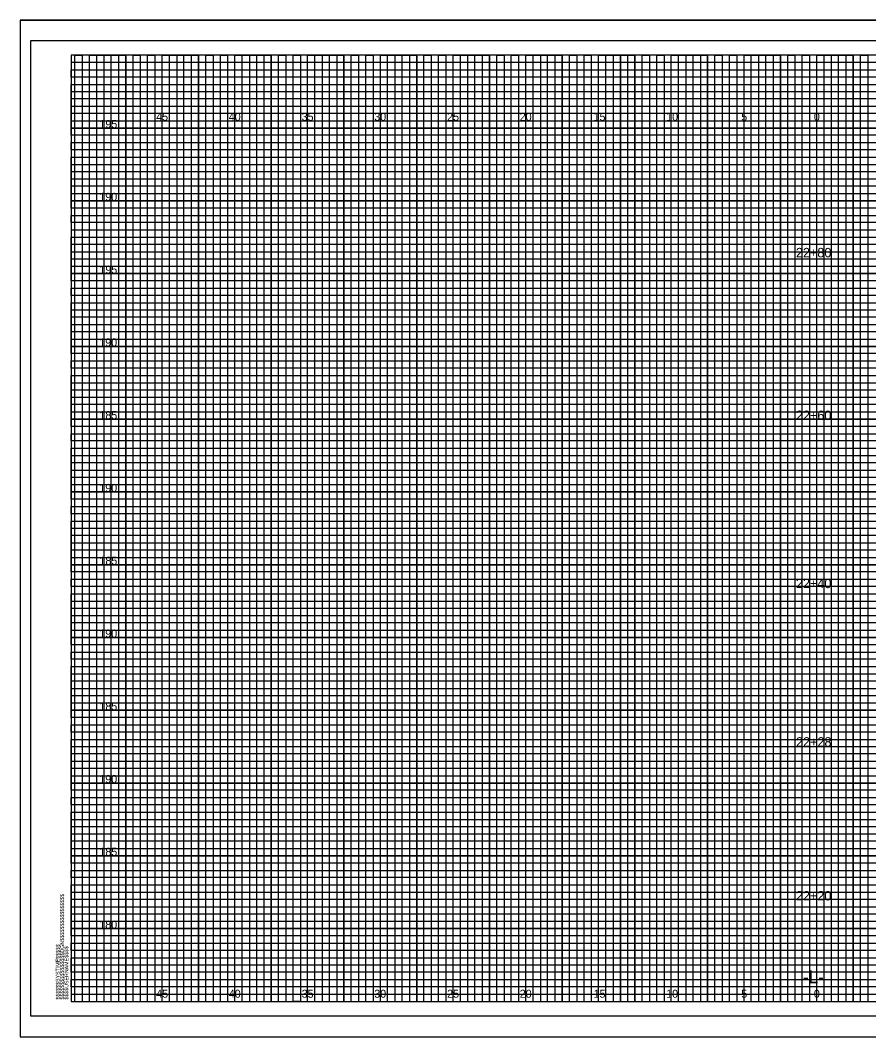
# Model space of a CAD drawing. Extents: x -4 to 103, y -2 to 6583.
# Drawn here: x -3.5 to 54.8, y 1201.6 to 1271.4 of the extents above; entities that cross this region are included whole.
import ezdxf

# ---------------------------------------------------------------- set-up
doc = ezdxf.new("R2010")
doc.units = 0
for name, color, linetype in [('Prop XS Alignment Label', 7, 'Continuous'), ('Prop XS Elevation Labels', 7, 'Continuous'), ('Prop XS Offset Labels', 7, 'Continuous'), ('Prop XS Station Labels', 7, 'Continuous'), ('Sheet Cross Section CELL', 7, 'Continuous'), ('Sheet Cross Section Grid Major CELL', 7, 'Continuous'), ('Sheet Cross Section Grid Middle CELL', 7, 'Continuous'), ('Sheet Cutting Line CELL', 7, 'Continuous'), ('Sheet DOT Grid CELL', 7, 'Continuous'), ('Sheet Plot Border Inside CELL', 7, 'Continuous'), ('Sheet Plot Border Outside CELL', 7, 'Continuous')]:
    doc.layers.add(name, color=color, linetype=linetype)

msp = doc.modelspace()

# ---------------------------------------------------------------- linework, layer by layer
at = {"layer": 'Sheet Cross Section CELL'}
msp.add_lwpolyline([(102.5, 1269.025), (0, 1269.025), (0, 1204.025), (102.5, 1204.025)], close=True, dxfattribs=at)
at = {"layer": 'Sheet Cross Section Grid Major CELL'}
for points in [[(1.25, 1204.025), (1.25, 1269.025), (3.75, 1269.025), (3.75, 1204.025), (6.25, 1204.025), (6.25, 1269.025), (8.75, 1269.025), (8.75, 1204.025), (11.25, 1204.025), (11.25, 1269.025), (13.75, 1269.025), (13.75, 1204.025), (16.25, 1204.025), (16.25, 1269.025), (18.75, 1269.025), (18.75, 1204.025), (21.25, 1204.025), (21.25, 1269.025), (23.75, 1269.025), (23.75, 1204.025), (26.25, 1204.025), (26.25, 1269.025), (28.75, 1269.025), (28.75, 1204.025), (31.25, 1204.025), (31.25, 1269.025), (33.75, 1269.025), (33.75, 1204.025), (36.25, 1204.025), (36.25, 1269.025), (38.75, 1269.025), (38.75, 1204.025), (41.25, 1204.025), (41.25, 1269.025), (43.75, 1269.025), (43.75, 1204.025), (46.25, 1204.025), (46.25, 1269.025), (48.75, 1269.025), (48.75, 1204.025), (51.25, 1204.025), (51.25, 1269.025), (53.75, 1269.025), (53.75, 1204.025)], [(102.5, 1264.025), (0, 1264.025), (0, 1266.525), (74.25, 1266.525)], [(102.5, 1259.025), (0, 1259.025), (0, 1261.525), (102.5, 1261.525)], [(102.5, 1254.025), (0, 1254.025), (0, 1256.525), (102.5, 1256.525)], [(102.5, 1249.025), (0, 1249.025), (0, 1251.525), (102.5, 1251.525)], [(102.5, 1244.025), (0, 1244.025), (0, 1246.525), (102.5, 1246.525)], [(102.5, 1239.025), (0, 1239.025), (0, 1241.525), (102.5, 1241.525)], [(102.5, 1234.025), (0, 1234.025), (0, 1236.525), (102.5, 1236.525)], [(102.5, 1229.025), (0, 1229.025), (0, 1231.525), (102.5, 1231.525)], [(102.5, 1224.025), (0, 1224.025), (0, 1226.525), (102.5, 1226.525)], [(102.5, 1219.025), (0, 1219.025), (0, 1221.525), (102.5, 1221.525)], [(102.5, 1214.025), (0, 1214.025), (0, 1216.525), (102.5, 1216.525)], [(102.5, 1209.025), (0, 1209.025), (0, 1211.525), (102.5, 1211.525)], [(0, 1206.525), (102.5, 1206.525)]]:
    msp.add_lwpolyline(points, dxfattribs=at)
at = {"layer": 'Sheet Cross Section Grid Middle CELL'}
for points in [[(0.25, 1204.025), (0.25, 1269.025), (0.75, 1269.025), (0.75, 1204.025), (1.75, 1204.025), (1.75, 1269.025), (2.25, 1269.025), (2.25, 1204.025), (2.75, 1204.025), (2.75, 1269.025), (3.25, 1269.025), (3.25, 1204.025), (4.25, 1204.025), (4.25, 1269.025), (4.75, 1269.025), (4.75, 1204.025), (5.25, 1204.025), (5.25, 1269.025), (5.75, 1269.025), (5.75, 1204.025), (6.75, 1204.025), (6.75, 1269.025), (7.25, 1269.025), (7.25, 1204.025), (7.75, 1204.025), (7.75, 1269.025), (8.25, 1269.025), (8.25, 1204.025), (9.25, 1204.025), (9.25, 1269.025), (9.75, 1269.025), (9.75, 1204.025), (10.25, 1204.025), (10.25, 1269.025), (10.75, 1269.025), (10.75, 1204.025), (11.75, 1204.025), (11.75, 1269.025), (12.25, 1269.025), (12.25, 1204.025), (12.75, 1204.025), (12.75, 1269.025), (13.25, 1269.025), (13.25, 1204.025), (14.25, 1204.025), (14.25, 1269.025), (14.75, 1269.025), (14.75, 1204.025), (15.75, 1204.025), (15.25, 1204.025), (15.25, 1269.025), (15.75, 1269.025), (15.75, 1204.025), (16.75, 1204.025), (16.75, 1269.025), (17.25, 1269.025), (17.25, 1204.025), (17.75, 1204.025), (17.75, 1269.025), (18.25, 1269.025), (18.25, 1204.025), (19.25, 1204.025), (19.25, 1269.025), (19.75, 1269.025), (19.75, 1204.025), (20.25, 1204.025), (20.25, 1269.025), (20.75, 1269.025), (20.75, 1204.025), (21.75, 1204.025), (21.75, 1269.025), (22.25, 1269.025), (22.25, 1204.025), (22.75, 1204.025), (22.75, 1269.025), (23.25, 1269.025), (23.25, 1204.025), (24.25, 1204.025), (24.25, 1269.025), (24.75, 1269.025), (24.75, 1204.025), (25.25, 1204.025), (25.25, 1269.025), (25.75, 1269.025), (25.75, 1204.025), (26.75, 1204.025), (26.75, 1269.025), (27.25, 1269.025), (27.25, 1204.025), (27.75, 1204.025), (27.75, 1269.025), (28.25, 1269.025), (28.25, 1204.025), (29.25, 1204.025), (29.25, 1269.025), (29.75, 1269.025), (29.75, 1204.025), (30.25, 1204.025), (30.25, 1269.025), (30.75, 1269.025), (30.75, 1204.025)], [(30.75, 1204.025), (31.75, 1204.025), (31.75, 1269.025), (32.25, 1269.025), (32.25, 1204.025), (32.75, 1204.025), (32.75, 1269.025), (33.25, 1269.025), (33.25, 1204.025), (34.25, 1204.025), (34.25, 1269.025), (34.75, 1269.025), (34.75, 1204.025), (35.25, 1204.025), (35.25, 1269.025), (35.75, 1269.025), (35.75, 1204.025), (36.75, 1204.025), (36.75, 1269.025), (37.25, 1269.025), (37.25, 1204.025), (37.75, 1204.025), (37.75, 1269.025), (37.75, 1204.025)], [(38.25, 1269.025), (38.25, 1204.025), (39.25, 1204.025), (39.25, 1269.025), (39.75, 1269.025), (39.75, 1204.025), (40.25, 1204.025), (40.25, 1269.025), (40.75, 1269.025), (40.75, 1204.025), (41.75, 1204.025), (41.75, 1269.025), (42.25, 1269.025), (42.25, 1204.025), (42.75, 1204.025), (42.75, 1269.025), (43.25, 1269.025), (43.25, 1204.025), (43.75, 1204.025), (44.25, 1204.025), (44.25, 1269.025), (44.75, 1269.025), (44.75, 1204.025), (45.25, 1204.025), (45.25, 1269.025), (45.75, 1269.025), (45.75, 1204.025), (46.75, 1204.025), (46.75, 1269.025), (47.25, 1269.025), (47.25, 1204.025), (47.75, 1204.025), (47.75, 1269.025), (48.25, 1269.025), (48.25, 1204.025), (49.25, 1204.025), (49.25, 1269.025), (49.75, 1269.025), (49.75, 1204.025), (50.25, 1204.025), (50.25, 1269.025), (50.75, 1269.025), (50.75, 1204.025), (51.75, 1204.025), (51.75, 1269.025), (52.25, 1269.025), (52.25, 1204.025), (52.75, 1204.025), (52.75, 1269.025), (53.25, 1269.025), (53.25, 1204.025), (54.25, 1204.025), (54.25, 1269.025), (54.75, 1269.025), (54.75, 1204.025), (55.25, 1204.025)], [(0, 1266.025), (0, 1267.025), (74.25, 1267.025), (74.25, 1267.525), (0, 1267.525), (0, 1268.025), (74.25, 1268.025), (74.25, 1268.525), (0, 1268.525)], [(102.5, 1266.025), (0, 1266.025)], [(102.5, 1265.025), (0, 1265.025), (0, 1265.525), (102.5, 1265.525)], [(102.5, 1263.525), (0, 1263.525), (0, 1264.525), (102.5, 1264.525)], [(102.5, 1262.525), (0, 1262.525), (0, 1263.025), (102.5, 1263.025)], [(102.5, 1261.025), (0, 1261.025), (0, 1262.025), (102.5, 1262.025)], [(102.5, 1260.025), (0, 1260.025), (0, 1260.525), (102.5, 1260.525)], [(102.5, 1258.525), (0, 1258.525), (0, 1259.525), (102.5, 1259.525)], [(102.5, 1257.525), (0, 1257.525), (0, 1258.025), (102.5, 1258.025)], [(0, 1257.025), (102.5, 1257.025)], [(102.5, 1256.025), (0, 1256.025)], [(102.5, 1255.025), (0, 1255.025), (0, 1255.525), (102.5, 1255.525)], [(102.5, 1253.525), (0, 1253.525), (0, 1254.525), (102.5, 1254.525)], [(102.5, 1252.525), (0, 1252.525), (0, 1253.025), (102.5, 1253.025)], [(102.5, 1251.025), (0, 1251.025), (0, 1252.025), (102.5, 1252.025)], [(102.5, 1250.025), (0, 1250.025), (0, 1250.525), (102.5, 1250.525)], [(102.5, 1248.525), (0, 1248.525), (0, 1249.525), (102.5, 1249.525)], [(102.5, 1247.525), (0, 1247.525), (0, 1248.025), (102.5, 1248.025)], [(102.5, 1246.025), (0, 1246.025), (0, 1247.025), (102.5, 1247.025)], [(102.5, 1245.025), (0, 1245.025), (0, 1245.525), (102.5, 1245.525)], [(102.5, 1243.525), (0, 1243.525), (0, 1244.525), (102.5, 1244.525)], [(102.5, 1242.525), (0, 1242.525), (0, 1243.025), (102.5, 1243.025)], [(102.5, 1241.025), (0, 1241.025), (0, 1242.025), (102.5, 1242.025)], [(102.5, 1240.025), (0, 1240.025), (0, 1240.525), (102.5, 1240.525)], [(102.5, 1238.525), (0, 1238.525), (0, 1239.525), (102.5, 1239.525)], [(102.5, 1237.525), (0, 1237.525), (0, 1238.025), (102.5, 1238.025)], [(102.5, 1236.025), (0, 1236.025), (0, 1237.025), (102.5, 1237.025)], [(102.5, 1235.025), (0, 1235.025), (0, 1235.525)], [(0, 1235.525), (102.5, 1235.525)], [(102.5, 1233.525), (0, 1233.525), (0, 1234.525), (102.5, 1234.525)], [(102.5, 1232.525), (0, 1232.525), (0, 1233.025), (102.5, 1233.025)], [(102.5, 1231.025), (0, 1231.025), (0, 1232.025), (102.5, 1232.025)], [(102.5, 1230.025), (0, 1230.025), (0, 1230.525), (102.5, 1230.525)], [(102.5, 1228.525), (0, 1228.525), (0, 1229.525), (102.5, 1229.525)], [(102.5, 1227.525), (0, 1227.525), (0, 1228.025), (102.5, 1228.025)], [(102.5, 1226.025), (0, 1226.025), (0, 1227.025), (102.5, 1227.025)], [(102.5, 1225.025), (0, 1225.025), (0, 1225.525), (102.5, 1225.525)], [(102.5, 1223.525), (0, 1223.525), (0, 1224.525), (102.5, 1224.525)], [(102.5, 1222.525), (0, 1222.525), (0, 1223.025), (102.5, 1223.025)], [(102.5, 1221.025), (0, 1221.025), (0, 1222.025), (102.5, 1222.025)], [(102.5, 1220.025), (0, 1220.025), (0, 1220.525), (102.5, 1220.525)], [(102.5, 1218.525), (0, 1218.525), (0, 1219.525), (102.5, 1219.525)], [(102.5, 1217.525), (0, 1217.525), (0, 1218.025), (102.5, 1218.025)], [(102.5, 1216.025), (0, 1216.025), (0, 1217.025), (102.5, 1217.025)], [(102.5, 1215.025), (0, 1215.025), (0, 1215.525), (102.5, 1215.525)], [(102.5, 1213.525), (0, 1213.525), (0, 1214.525), (102.5, 1214.525)], [(102.5, 1212.525), (0, 1212.525), (0, 1213.025), (102.5, 1213.025)], [(102.5, 1211.025), (0, 1211.025), (0, 1212.025), (102.5, 1212.025)], [(102.5, 1210.025), (0, 1210.025), (0, 1210.525), (102.5, 1210.525)], [(102.5, 1208.525), (0, 1208.525), (0, 1209.525), (102.5, 1209.525)], [(102.5, 1207.525), (0, 1207.525), (0, 1208.025), (102.5, 1208.025)], [(102.5, 1206.025), (0, 1206.025), (0, 1207.025), (102.5, 1207.025)], [(102.5, 1205.025), (0, 1205.025), (0, 1205.525), (102.5, 1205.525)], [(0, 1204.525), (102.5, 1204.525)]]:
    msp.add_lwpolyline(points, dxfattribs=at)
at = {"layer": 'Sheet Cutting Line CELL'}
for p, q in [((-3.5, 1271.425), (103.4, 1271.425)), ((-3.5, 1271.425), (-3.5, 1201.6)), ((-3.5, 1201.6), (103.4, 1201.6))]:
    msp.add_line(p, q, dxfattribs=at)
at = {"layer": 'Sheet DOT Grid CELL'}
for p, q in [((1.25, 1204.025), (1.25, 1269.025)), ((3.75, 1204.025), (3.75, 1269.025)), ((6.25, 1204.025), (6.25, 1269.025)), ((8.75, 1204.025), (8.75, 1269.025)), ((11.25, 1204.025), (11.25, 1269.025)), ((13.75, 1204.025), (13.75, 1269.025)), ((16.25, 1204.025), (16.25, 1269.025)), ((18.75, 1204.025), (18.75, 1269.025)), ((21.25, 1204.025), (21.25, 1269.025)), ((23.75, 1204.025), (23.75, 1269.025)), ((26.25, 1204.025), (26.25, 1269.025)), ((28.75, 1204.025), (28.75, 1269.025)), ((31.25, 1204.025), (31.25, 1269.025)), ((33.75, 1204.025), (33.75, 1269.025)), ((36.25, 1204.025), (36.25, 1269.025)), ((38.75, 1204.025), (38.75, 1269.025)), ((41.25, 1204.025), (41.25, 1269.025)), ((43.75, 1204.025), (43.75, 1269.025)), ((46.25, 1204.025), (46.25, 1269.025)), ((48.75, 1204.025), (48.75, 1269.025)), ((51.25, 1204.025), (51.25, 1269.025)), ((53.75, 1204.025), (53.75, 1269.025)), ((0, 1266.525), (74.25, 1266.525)), ((0, 1264.025), (102.5, 1264.025)), ((0, 1261.525), (102.5, 1261.525)), ((0, 1259.025), (102.5, 1259.025)), ((0, 1256.525), (102.5, 1256.525)), ((0, 1254.025), (102.5, 1254.025)), ((0, 1251.525), (102.5, 1251.525)), ((0, 1249.025), (102.5, 1249.025)), ((0, 1246.525), (102.5, 1246.525)), ((0, 1244.025), (102.5, 1244.025)), ((0, 1241.525), (102.5, 1241.525)), ((0, 1239.025), (102.5, 1239.025)), ((0, 1236.525), (102.5, 1236.525)), ((0, 1234.025), (102.5, 1234.025)), ((0, 1231.525), (102.5, 1231.525)), ((0, 1229.025), (102.5, 1229.025)), ((0, 1226.525), (102.5, 1226.525)), ((0, 1224.025), (102.5, 1224.025)), ((0, 1221.525), (102.5, 1221.525)), ((0, 1219.025), (102.5, 1219.025)), ((0, 1216.525), (102.5, 1216.525)), ((0, 1214.025), (102.5, 1214.025)), ((0, 1211.525), (102.5, 1211.525)), ((0, 1209.025), (102.5, 1209.025)), ((0, 1206.525), (102.5, 1206.525))]:
    msp.add_line(p, q, dxfattribs=at)
at = {"layer": 'Sheet Plot Border Inside CELL'}
msp.add_lwpolyline([(103, 1270.025), (-2.8, 1270.025), (-2.8, 1203.025), (103, 1203.025)], close=True, dxfattribs=at)
at = {"layer": 'Sheet Plot Border Outside CELL'}
msp.add_lwpolyline([(103.4, 1271.425), (-3.5, 1271.425), (-3.5, 1201.6), (103.4, 1201.6)], close=True, dxfattribs=at)

# ---------------------------------------------------------------- texts
at = {"layer": 'Prop XS Alignment Label'}
msp.add_text('-L-', height=0.875, dxfattribs=at).set_placement((50.307, 1205.275))
at = {"layer": 'Prop XS Elevation Labels'}
for s, p in [('195', (1.938, 1264.025)), ('190', (1.93, 1259.025)), ('195', (1.938, 1254.025)), ('190', (1.93, 1249.025)), ('185', (1.938, 1244.025)), ('190', (1.93, 1239.025)), ('185', (1.938, 1234.025)), ('190', (1.93, 1229.025)), ('185', (1.938, 1224.025)), ('190', (1.93, 1219.025)), ('185', (1.938, 1214.025)), ('180', (1.93, 1209.025))]:
    msp.add_text(s, height=0.55, dxfattribs=at).set_placement(p)
at = {"layer": 'Prop XS Offset Labels'}
for s, p in [('45', (5.84, 1264.525)), ('40', (10.831, 1264.525)), ('35', (15.84, 1264.525)), ('30', (20.831, 1264.525)), ('25', (25.84, 1264.525)), ('20', (30.831, 1264.525)), ('15', (35.906, 1264.525)), ('10', (40.897, 1264.525)), ('5', (46.057, 1264.525)), ('0', (51.049, 1264.525)), ('0', (51.049, 1264.525)), ('45', (5.84, 1204.275)), ('40', (10.831, 1204.275)), ('35', (15.84, 1204.275)), ('30', (20.831, 1204.275)), ('25', (25.84, 1204.275)), ('20', (30.831, 1204.275)), ('15', (35.906, 1204.275)), ('10', (40.897, 1204.275)), ('5', (46.057, 1204.275)), ('0', (51.049, 1204.275)), ('0', (51.049, 1204.275))]:
    msp.add_text(s, height=0.55, dxfattribs=at).set_placement(p)
at = {"layer": 'Prop XS Station Labels'}
for s, p in [('22+80', (49.816, 1255.141)), ('22+60', (49.816, 1243.963)), ('22+40', (49.816, 1232.415)), ('22+28', (49.821, 1221.524)), ('22+20', (49.816, 1210.956))]:
    msp.add_text(s, height=0.65, dxfattribs=at).set_placement(p)
at = {"layer": 'Sheet Cross Section CELL'}
for s, p in [('$$$$$$$$$$$$$$$$DGN$$$$$$$$$$$$$$$$', (-0.5, 1204.15)), ('$$$$$$SYSTIME$$$$$', (-0.797, 1204.15)), ('$$$$USERNAME$$$$', (-0.2, 1204.15))]:
    msp.add_text(s, height=0.2625, rotation=90, dxfattribs=at).set_placement(p)
at = {"layer": 'Sheet Cross Section Grid Major CELL'}
msp.add_text('040397', height=0.0025, rotation=90, dxfattribs=at).set_placement((-0.001, 1269.011))

doc.saveas('drawing.dxf')
